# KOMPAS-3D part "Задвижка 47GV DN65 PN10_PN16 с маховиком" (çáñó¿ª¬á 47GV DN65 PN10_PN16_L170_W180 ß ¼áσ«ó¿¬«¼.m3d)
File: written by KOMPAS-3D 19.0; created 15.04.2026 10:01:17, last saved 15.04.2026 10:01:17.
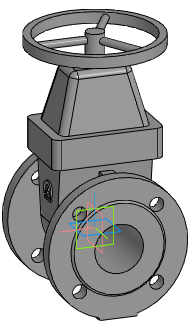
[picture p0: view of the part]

Document properties: Автор: Евгений; Полное имя файла: Z:\3.Личные\kachalov\3d для проектировщиков\2.1 Тип 47GV, 47GV.Z\Задвижка 47GV_DN40-DN600\stp_Задвижка 47GV\Задвижка 47GV DN65 PN10_PN16_L170_W180 с маховиком.m3d

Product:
- Part/product: Задвижка 47GV DN65 PN10_PN16 с маховиком

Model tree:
1. Операция без истории:1  (labels: Задвижка 47GV DN65 PN10_PN16 с маховиком)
